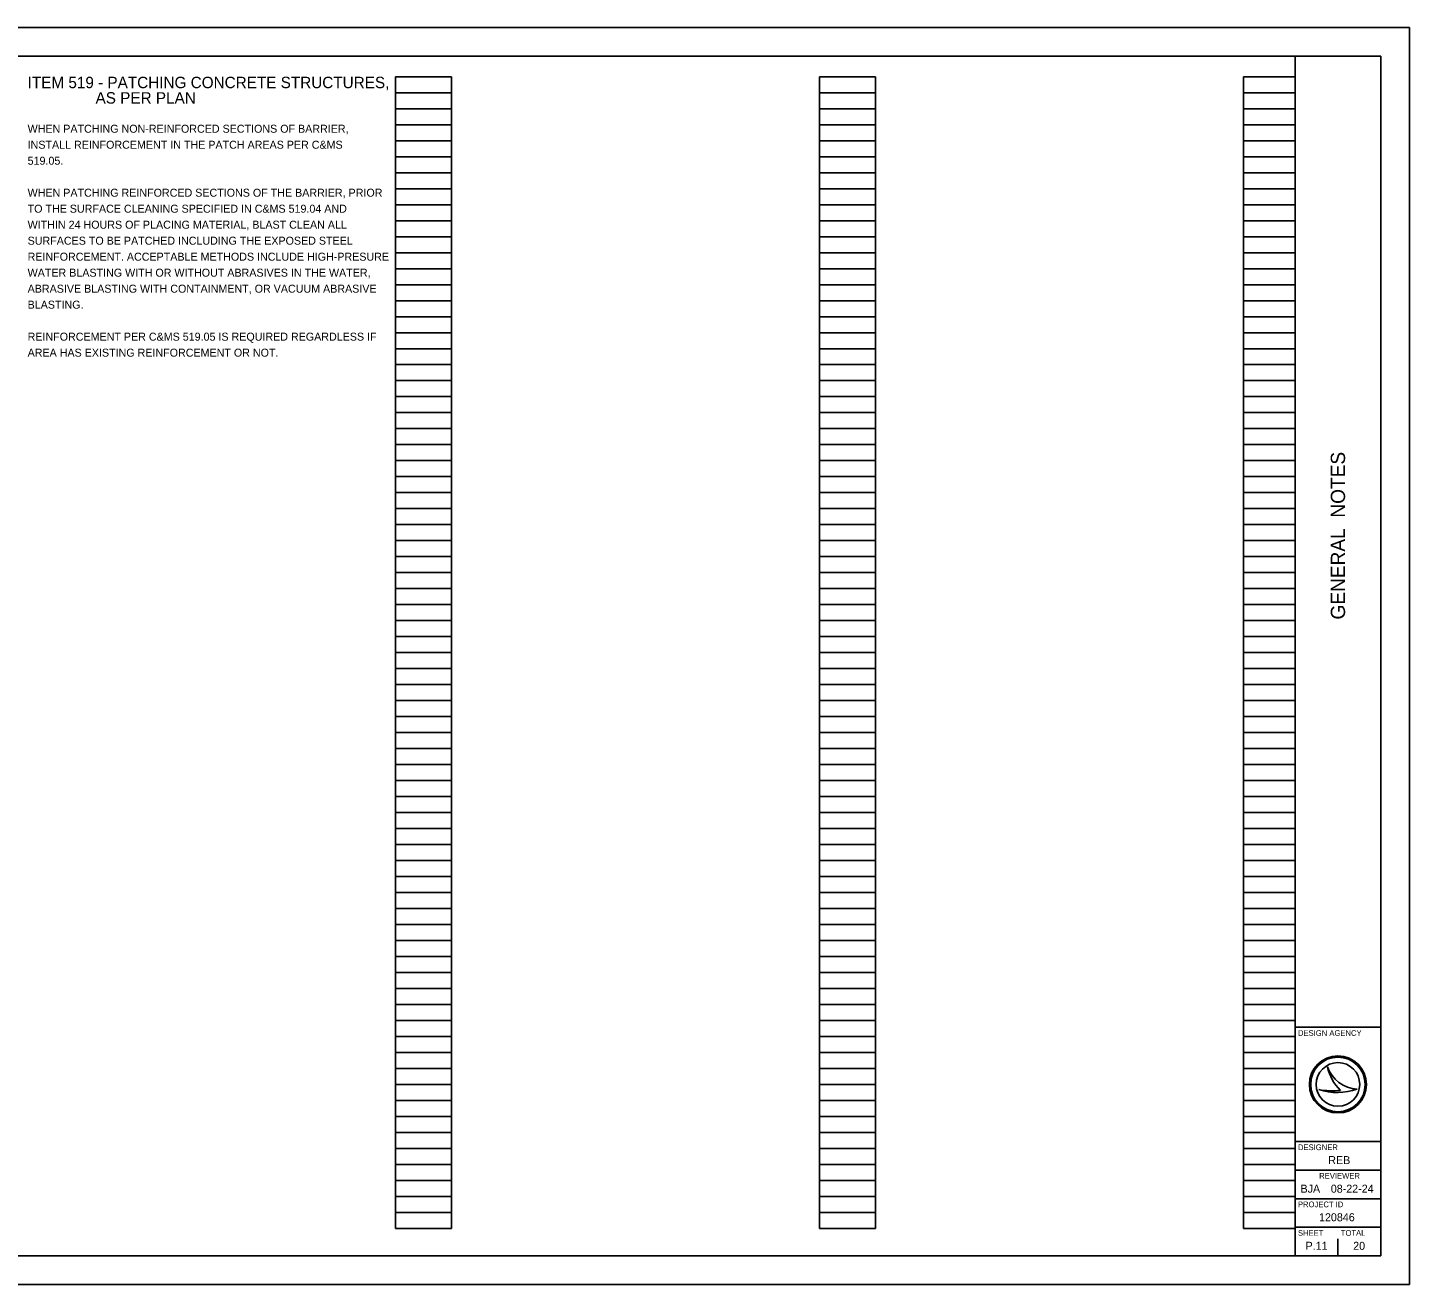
# Model space of a CAD drawing. Extents: x -8.2 to 34, y 0 to 22.
# Drawn here: x 9.82 to 34, y 0 to 22 of the extents above; entities that cross this region are included whole.
import ezdxf

# ---------------------------------------------------------------- set-up
doc = ezdxf.new("R2010")
doc.units = 0
for name, color, linetype in [('Default', 7, 'Continuous'), ('SH_Border', 7, 'Continuous'), ('SH_Cut_Line', 7, 'Continuous'), ('SH_Data', 7, 'Continuous'), ('SH_Text', 7, 'Continuous')]:
    doc.layers.add(name, color=color, linetype=linetype)

msp = doc.modelspace()

# ---------------------------------------------------------------- linework, layer by layer
at = {"layer": 'SH_Border'}
for p, q in [((32, 0.5), (32, 21.5)), ((32, 4.5), (33.5, 4.5)), ((32, 2.5), (33.5, 2.5)), ((32, 2), (33.5, 2)), ((32, 1.5), (33.5, 1.5)), ((32, 1), (33.5, 1))]:
    msp.add_line(p, q, dxfattribs=at)
msp.add_lwpolyline([(1.5, 21.5), (33.5, 21.5), (33.5, 0.5), (1.5, 0.5)], close=True, dxfattribs=at)
at = {"layer": 'SH_Cut_Line'}
msp.add_lwpolyline([(0, 0), (34, 0), (34, 22), (0, 22)], close=True, dxfattribs=at)
at = {"layer": 'SH_Data'}
for p, q in [((16.26, 0.98), (16.26, 21.14)), ((16.26, 21.14), (17.24, 21.14)), ((17.24, 0.98), (17.24, 21.14)), ((23.68, 0.98), (23.68, 21.14)), ((23.68, 21.14), (24.66, 21.14)), ((24.66, 0.98), (24.66, 21.14)), ((31.1, 0.98), (31.1, 21.14)), ((31.1, 21.14), (32, 21.14)), ((32, 0.98), (32, 21.14)), ((16.26, 20.86), (17.24, 20.86)), ((23.68, 20.86), (24.66, 20.86)), ((31.1, 20.86), (32, 20.86)), ((16.26, 20.58), (17.24, 20.58)), ((23.68, 20.58), (24.66, 20.58)), ((31.1, 20.58), (32, 20.58)), ((16.26, 20.3), (17.24, 20.3)), ((23.68, 20.3), (24.66, 20.3)), ((31.1, 20.3), (32, 20.3)), ((16.26, 20.02), (17.24, 20.02)), ((23.68, 20.02), (24.66, 20.02)), ((31.1, 20.02), (32, 20.02)), ((16.26, 19.74), (17.24, 19.74)), ((23.68, 19.74), (24.66, 19.74)), ((31.1, 19.74), (32, 19.74)), ((16.26, 19.46), (17.24, 19.46)), ((23.68, 19.46), (24.66, 19.46)), ((31.1, 19.46), (32, 19.46)), ((16.26, 19.18), (17.24, 19.18)), ((23.68, 19.18), (24.66, 19.18)), ((31.1, 19.18), (32, 19.18)), ((16.26, 18.9), (17.24, 18.9)), ((23.68, 18.9), (24.66, 18.9)), ((31.1, 18.9), (32, 18.9)), ((16.26, 18.62), (17.24, 18.62)), ((23.68, 18.62), (24.66, 18.62)), ((31.1, 18.62), (32, 18.62)), ((16.26, 18.34), (17.24, 18.34)), ((23.68, 18.34), (24.66, 18.34)), ((31.1, 18.34), (32, 18.34)), ((16.26, 18.06), (17.24, 18.06)), ((23.68, 18.06), (24.66, 18.06)), ((31.1, 18.06), (32, 18.06)), ((16.26, 17.78), (17.24, 17.78)), ((23.68, 17.78), (24.66, 17.78)), ((31.1, 17.78), (32, 17.78)), ((16.26, 17.5), (17.24, 17.5)), ((23.68, 17.5), (24.66, 17.5)), ((31.1, 17.5), (32, 17.5)), ((16.26, 17.22), (17.24, 17.22)), ((23.68, 17.22), (24.66, 17.22)), ((31.1, 17.22), (32, 17.22)), ((16.26, 16.94), (17.24, 16.94)), ((23.68, 16.94), (24.66, 16.94)), ((31.1, 16.94), (32, 16.94)), ((16.26, 16.66), (17.24, 16.66)), ((23.68, 16.66), (24.66, 16.66)), ((31.1, 16.66), (32, 16.66)), ((16.26, 16.38), (17.24, 16.38)), ((23.68, 16.38), (24.66, 16.38)), ((31.1, 16.38), (32, 16.38)), ((16.26, 16.1), (17.24, 16.1)), ((23.68, 16.1), (24.66, 16.1)), ((31.1, 16.1), (32, 16.1)), ((16.26, 15.82), (17.24, 15.82)), ((23.68, 15.82), (24.66, 15.82)), ((31.1, 15.82), (32, 15.82)), ((16.26, 15.54), (17.24, 15.54)), ((23.68, 15.54), (24.66, 15.54)), ((31.1, 15.54), (32, 15.54)), ((16.26, 15.26), (17.24, 15.26)), ((23.68, 15.26), (24.66, 15.26)), ((31.1, 15.26), (32, 15.26)), ((16.26, 14.98), (17.24, 14.98)), ((23.68, 14.98), (24.66, 14.98)), ((31.1, 14.98), (32, 14.98)), ((16.26, 14.7), (17.24, 14.7)), ((23.68, 14.7), (24.66, 14.7)), ((31.1, 14.7), (32, 14.7)), ((16.26, 14.42), (17.24, 14.42)), ((23.68, 14.42), (24.66, 14.42)), ((31.1, 14.42), (32, 14.42)), ((16.26, 14.14), (17.24, 14.14)), ((23.68, 14.14), (24.66, 14.14)), ((31.1, 14.14), (32, 14.14)), ((16.26, 13.86), (17.24, 13.86)), ((23.68, 13.86), (24.66, 13.86)), ((31.1, 13.86), (32, 13.86)), ((16.26, 13.58), (17.24, 13.58)), ((23.68, 13.58), (24.66, 13.58)), ((31.1, 13.58), (32, 13.58)), ((16.26, 13.3), (17.24, 13.3)), ((23.68, 13.3), (24.66, 13.3)), ((31.1, 13.3), (32, 13.3)), ((16.26, 13.02), (17.24, 13.02)), ((23.68, 13.02), (24.66, 13.02)), ((31.1, 13.02), (32, 13.02)), ((16.26, 12.74), (17.24, 12.74)), ((23.68, 12.74), (24.66, 12.74)), ((31.1, 12.74), (32, 12.74)), ((16.26, 12.46), (17.24, 12.46)), ((23.68, 12.46), (24.66, 12.46)), ((31.1, 12.46), (32, 12.46)), ((16.26, 12.18), (17.24, 12.18)), ((23.68, 12.18), (24.66, 12.18)), ((31.1, 12.18), (32, 12.18)), ((16.26, 11.9), (17.24, 11.9)), ((23.68, 11.9), (24.66, 11.9)), ((31.1, 11.9), (32, 11.9)), ((16.26, 11.62), (17.24, 11.62)), ((23.68, 11.62), (24.66, 11.62)), ((31.1, 11.62), (32, 11.62)), ((16.26, 11.34), (17.24, 11.34)), ((23.68, 11.34), (24.66, 11.34)), ((31.1, 11.34), (32, 11.34)), ((16.26, 11.06), (17.24, 11.06)), ((23.68, 11.06), (24.66, 11.06)), ((31.1, 11.06), (32, 11.06)), ((16.26, 10.78), (17.24, 10.78)), ((23.68, 10.78), (24.66, 10.78)), ((31.1, 10.78), (32, 10.78)), ((16.26, 10.5), (17.24, 10.5)), ((23.68, 10.5), (24.66, 10.5)), ((31.1, 10.5), (32, 10.5)), ((16.26, 10.22), (17.24, 10.22)), ((23.68, 10.22), (24.66, 10.22)), ((31.1, 10.22), (32, 10.22)), ((16.26, 9.94), (17.24, 9.94)), ((23.68, 9.94), (24.66, 9.94)), ((31.1, 9.94), (32, 9.94)), ((16.26, 9.66), (17.24, 9.66)), ((23.68, 9.66), (24.66, 9.66)), ((31.1, 9.66), (32, 9.66)), ((16.26, 9.38), (17.24, 9.38)), ((23.68, 9.38), (24.66, 9.38)), ((31.1, 9.38), (32, 9.38)), ((16.26, 9.1), (17.24, 9.1)), ((23.68, 9.1), (24.66, 9.1)), ((31.1, 9.1), (32, 9.1)), ((16.26, 8.82), (17.24, 8.82)), ((23.68, 8.82), (24.66, 8.82)), ((31.1, 8.82), (32, 8.82)), ((16.26, 8.54), (17.24, 8.54)), ((23.68, 8.54), (24.66, 8.54)), ((31.1, 8.54), (32, 8.54)), ((16.26, 8.26), (17.24, 8.26)), ((23.68, 8.26), (24.66, 8.26)), ((31.1, 8.26), (32, 8.26)), ((16.26, 7.98), (17.24, 7.98)), ((23.68, 7.98), (24.66, 7.98)), ((31.1, 7.98), (32, 7.98)), ((16.26, 7.7), (17.24, 7.7)), ((23.68, 7.7), (24.66, 7.7)), ((31.1, 7.7), (32, 7.7)), ((16.26, 7.42), (17.24, 7.42)), ((23.68, 7.42), (24.66, 7.42)), ((31.1, 7.42), (32, 7.42)), ((16.26, 7.14), (17.24, 7.14)), ((23.68, 7.14), (24.66, 7.14)), ((31.1, 7.14), (32, 7.14)), ((16.26, 6.86), (17.24, 6.86)), ((23.68, 6.86), (24.66, 6.86)), ((31.1, 6.86), (32, 6.86)), ((16.26, 6.58), (17.24, 6.58)), ((23.68, 6.58), (24.66, 6.58)), ((31.1, 6.58), (32, 6.58)), ((16.26, 6.3), (17.24, 6.3)), ((23.68, 6.3), (24.66, 6.3)), ((31.1, 6.3), (32, 6.3)), ((16.26, 6.02), (17.24, 6.02)), ((23.68, 6.02), (24.66, 6.02)), ((31.1, 6.02), (32, 6.02)), ((16.26, 5.74), (17.24, 5.74)), ((23.68, 5.74), (24.66, 5.74)), ((31.1, 5.74), (32, 5.74)), ((16.26, 5.46), (17.24, 5.46)), ((23.68, 5.46), (24.66, 5.46)), ((31.1, 5.46), (32, 5.46)), ((16.26, 5.18), (17.24, 5.18)), ((23.68, 5.18), (24.66, 5.18)), ((31.1, 5.18), (32, 5.18)), ((16.26, 4.9), (17.24, 4.9)), ((23.68, 4.9), (24.66, 4.9)), ((31.1, 4.9), (32, 4.9)), ((16.26, 4.62), (17.24, 4.62)), ((23.68, 4.62), (24.66, 4.62)), ((31.1, 4.62), (32, 4.62)), ((16.26, 4.34), (17.24, 4.34)), ((23.68, 4.34), (24.66, 4.34)), ((31.1, 4.34), (32, 4.34)), ((16.26, 4.06), (17.24, 4.06)), ((23.68, 4.06), (24.66, 4.06)), ((31.1, 4.06), (32, 4.06)), ((16.26, 3.78), (17.24, 3.78)), ((23.68, 3.78), (24.66, 3.78)), ((31.1, 3.78), (32, 3.78)), ((32.567, 3.81), (32.567, 3.81)), ((16.26, 3.5), (17.24, 3.5)), ((23.68, 3.5), (24.66, 3.5)), ((31.1, 3.5), (32, 3.5)), ((32.417, 3.41), (32.417, 3.41)), ((32.75, 3.5), (32.75, 3.5)), ((33.087, 3.419), (33.087, 3.419)), ((16.26, 3.22), (17.24, 3.22)), ((23.68, 3.22), (24.66, 3.22)), ((31.1, 3.22), (32, 3.22)), ((16.26, 2.94), (17.24, 2.94)), ((23.68, 2.94), (24.66, 2.94)), ((31.1, 2.94), (32, 2.94)), ((16.26, 2.66), (17.24, 2.66)), ((23.68, 2.66), (24.66, 2.66)), ((31.1, 2.66), (32, 2.66)), ((16.26, 2.38), (17.24, 2.38)), ((23.68, 2.38), (24.66, 2.38)), ((31.1, 2.38), (32, 2.38)), ((16.26, 2.1), (17.24, 2.1)), ((23.68, 2.1), (24.66, 2.1)), ((31.1, 2.1), (32, 2.1)), ((16.26, 1.82), (17.24, 1.82)), ((23.68, 1.82), (24.66, 1.82)), ((31.1, 1.82), (32, 1.82)), ((16.26, 1.54), (17.24, 1.54)), ((23.68, 1.54), (24.66, 1.54)), ((31.1, 1.54), (32, 1.54)), ((16.26, 1.26), (17.24, 1.26)), ((23.68, 1.26), (24.66, 1.26)), ((31.1, 1.26), (32, 1.26)), ((16.26, 0.98), (17.24, 0.98)), ((23.68, 0.98), (24.66, 0.98)), ((31.1, 0.98), (32, 0.98)), ((32.75, 0.5), (32.75, 0.8)), ((32.375, 0.675), (32.375, 0.675))]:
    msp.add_line(p, q, dxfattribs=at)
for radius in [0.5, 0.477, 0.477, 0.382]:
    msp.add_circle((32.75, 3.5), radius, dxfattribs=at)
for centre, radius, start, end in [((33.116, 3.998), 0.58, 198.9257, 198.9319), ((33.347, 3.97), 0.796, 191.6379, 191.6421), ((33.116, 3.998), 0.58, 198.9319, 267.1657), ((33.347, 3.97), 0.796, 191.6421, 226.0947), ((32.739, 4.37), 1.013, 251.4576, 290.0832), ((32.648, 4.654), 1.266, 259.4964, 259.4995), ((32.739, 4.37), 1.013, 251.4527, 251.4576), ((32.648, 4.654), 1.266, 259.4995, 276.6672)]:
    msp.add_arc(centre, radius, start, end, dxfattribs=at)

# ---------------------------------------------------------------- texts
at = {"layer": 'Default'}
for s, p in [('ITEM 519 - PATCHING CONCRETE STRUCTURES, ', (9.82, 20.94)), ('                AS PER PLAN', (9.82, 20.67))]:
    msp.add_text(s, height=0.2, dxfattribs=at).set_placement(p)
at = {"layer": 'SH_Data'}
msp.add_text('GENERAL  NOTES', height=0.25, rotation=90, dxfattribs=at).set_placement((32.875, 11.638))
for s, height, p in [('DESIGN AGENCY', 0.1, (32.05, 4.35)), ('DESIGNER', 0.1, (32.05, 2.35)), ('REB', 0.14, (32.581, 2.105)), ('REVIEWER', 0.1, (32.422, 1.85)), ('BJA', 0.14, (32.095, 1.605)), ('08-22-24', 0.14, (32.625, 1.605)), ('PROJECT ID', 0.1, (32.05, 1.35)), ('120846', 0.14, (32.419, 1.105)), ('SHEET', 0.1, (32.05, 0.85)), ('P.11', 0.14, (32.184, 0.605)), ('TOTAL', 0.1, (32.8, 0.85)), ('20', 0.14, (33.017, 0.605))]:
    msp.add_text(s, height=height, dxfattribs=at).set_placement(p)
at = {"layer": 'SH_Text'}
for s, p in [('WHEN PATCHING NON-REINFORCED SECTIONS OF BARRIER, ', (9.82, 20.16)), ('INSTALL REINFORCEMENT IN THE PATCH AREAS PER C&MS ', (9.82, 19.88)), ('519.05. ', (9.82, 19.6)), ('WHEN PATCHING REINFORCED SECTIONS OF THE BARRIER, PRIOR', (9.82, 19.04)), ('TO THE SURFACE CLEANING SPECIFIED IN C&MS 519.04 AND ', (9.82, 18.76)), ('WITHIN 24 HOURS OF PLACING MATERIAL, BLAST CLEAN ALL ', (9.82, 18.48)), ('SURFACES TO BE PATCHED INCLUDING THE EXPOSED STEEL ', (9.82, 18.2)), ('REINFORCEMENT. ACCEPTABLE METHODS INCLUDE HIGH-PRESURE ', (9.82, 17.92)), ('WATER BLASTING WITH OR WITHOUT ABRASIVES IN THE WATER, ', (9.82, 17.64)), ('ABRASIVE BLASTING WITH CONTAINMENT, OR VACUUM ABRASIVE ', (9.82, 17.36)), ('BLASTING.', (9.82, 17.08)), ('REINFORCEMENT PER C&MS 519.05 IS REQUIRED REGARDLESS IF ', (9.82, 16.52)), ('AREA HAS EXISTING REINFORCEMENT OR NOT.', (9.82, 16.24))]:
    msp.add_text(s, height=0.14, dxfattribs=at).set_placement(p)

doc.saveas('drawing.dxf')
